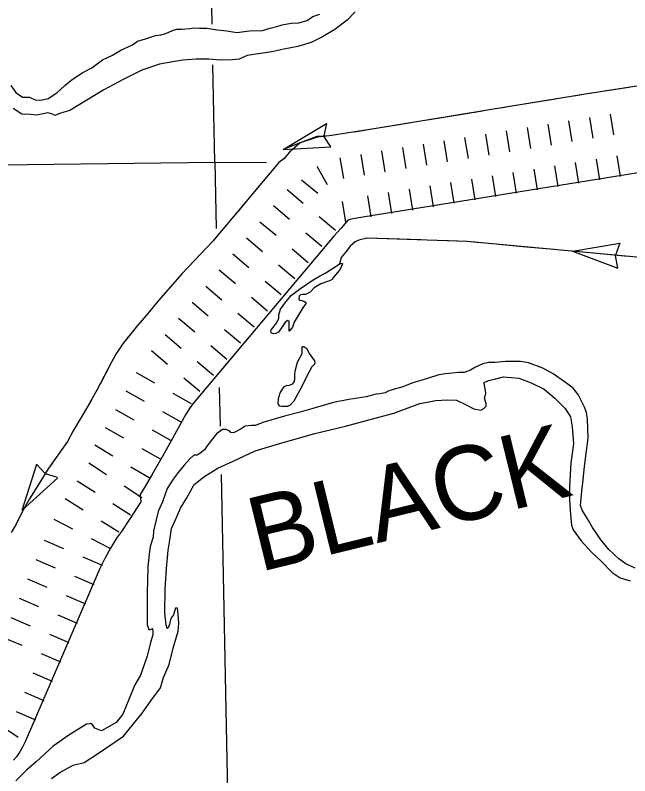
# Model space of a CAD drawing. Extents: x 1164457 to 1439835, y 1590918 to 1773502.
# Drawn here: x 1312624 to 1317004, y 1635733 to 1641151 of the extents above; entities that cross this region are included whole.
import ezdxf

# ---------------------------------------------------------------- set-up
doc = ezdxf.new("R2010")
doc.units = 0
for name, color, linetype in [('Level 29', 7, 'Continuous'), ('Level 35', 7, 'Continuous'), ('Level 43', 7, 'Continuous'), ('Level 5', 7, 'Continuous')]:
    doc.layers.add(name, color=color, linetype=linetype)

msp = doc.modelspace()

# ---------------------------------------------------------------- linework, layer by layer
at = {"layer": 'Level 29'}
for p, q in [((1316567.5, 1640398.1), (1316591.3, 1640250)), ((1316567.5, 1640398.1), (1316591.3, 1640250)), ((1316715.6, 1640421.9), (1316739.4, 1640273.9)), ((1316863.7, 1640445.8), (1316887.5, 1640297.7)), ((1316271.3, 1640350.4), (1316295.2, 1640202.3)), ((1316419.4, 1640374.2), (1316443.3, 1640226.1)), ((1315975.1, 1640302.6), (1315999, 1640154.6)), ((1316123.2, 1640326.5), (1316147.1, 1640178.4)), ((1316123.2, 1640326.5), (1316147.1, 1640178.4)), ((1315530.9, 1640231.1), (1315554.7, 1640083)), ((1315678.9, 1640254.9), (1315702.8, 1640106.8)), ((1315678.9, 1640254.9), (1315702.8, 1640106.8)), ((1315827, 1640278.8), (1315850.9, 1640130.7)), ((1315234.7, 1640183.4), (1315258.5, 1640035.3)), ((1315234.7, 1640183.4), (1315258.5, 1640035.3)), ((1315382.8, 1640207.2), (1315406.6, 1640059.1)), ((1314938.5, 1640135.6), (1314962.4, 1639987.5)), ((1315086.6, 1640159.5), (1315110.4, 1640011.4)), ((1316763.3, 1640125.8), (1316787.2, 1639977.7)), ((1316911.4, 1640149.6), (1316935.2, 1640001.5)), ((1314773.1, 1640075.7), (1314847.9, 1639945.6)), ((1316467.1, 1640078), (1316491, 1639930)), ((1316615.2, 1640101.9), (1316639.1, 1639953.8)), ((1316615.2, 1640101.9), (1316639.1, 1639953.8)), ((1316170.9, 1640030.3), (1316194.8, 1639882.2)), ((1316170.9, 1640030.3), (1316194.8, 1639882.2)), ((1316319, 1640054.2), (1316342.9, 1639906.1)), ((1314663.4, 1639977.1), (1314779.5, 1639882.1)), ((1315874.8, 1639982.6), (1315898.6, 1639834.5)), ((1316022.8, 1640006.5), (1316046.7, 1639858.4)), ((1314561.2, 1639909.4), (1314675.9, 1639812.8)), ((1315430.5, 1639911), (1315454.3, 1639762.9)), ((1315578.6, 1639934.9), (1315602.4, 1639786.8)), ((1315726.7, 1639958.8), (1315750.5, 1639810.7)), ((1315726.7, 1639958.8), (1315750.5, 1639810.7)), ((1315134.3, 1639863.3), (1315158.2, 1639715.2)), ((1315282.4, 1639887.2), (1315306.3, 1639739.1)), ((1315282.4, 1639887.2), (1315306.3, 1639739.1)), ((1314954.3, 1639823.5), (1314978.2, 1639675.4)), ((1314464.6, 1639794.7), (1314579.3, 1639698.1)), ((1314790.7, 1639716.2), (1314905.4, 1639619.6)), ((1314368, 1639679.9), (1314482.7, 1639583.3)), ((1314368, 1639679.9), (1314482.7, 1639583.3)), ((1314694.1, 1639601.5), (1314808.8, 1639504.9)), ((1314271.4, 1639565.2), (1314386.1, 1639468.6)), ((1314597.5, 1639486.7), (1314712.2, 1639390.1)), ((1314597.5, 1639486.7), (1314712.2, 1639390.1)), ((1314174.8, 1639450.4), (1314289.5, 1639353.8)), ((1314500.9, 1639372), (1314615.6, 1639275.3)), ((1314078.2, 1639335.7), (1314192.9, 1639239)), ((1314078.2, 1639335.7), (1314192.9, 1639239)), ((1314404.3, 1639257.2), (1314519, 1639160.6)), ((1313981.6, 1639220.9), (1314096.3, 1639124.3)), ((1313885, 1639106.1), (1313999.7, 1639009.5)), ((1314307.7, 1639142.4), (1314422.4, 1639045.8)), ((1314307.7, 1639142.4), (1314422.4, 1639045.8)), ((1313788.4, 1638991.4), (1313903.1, 1638894.8)), ((1313788.4, 1638991.4), (1313903.1, 1638894.8)), ((1314211.1, 1639027.7), (1314325.8, 1638931.1)), ((1313691.8, 1638876.6), (1313806.5, 1638780)), ((1314114.5, 1638912.9), (1314229.2, 1638816.3)), ((1314017.9, 1638798.2), (1314132.6, 1638701.6)), ((1314017.9, 1638798.2), (1314132.6, 1638701.6)), ((1313595, 1638761.6), (1313709.9, 1638665.2)), ((1313921.3, 1638683.4), (1314036, 1638586.8)), ((1313485, 1638605.2), (1313615.6, 1638531.5)), ((1313485, 1638605.2), (1313615.6, 1638531.5)), ((1313824.8, 1638568.7), (1313939.6, 1638472.3)), ((1313411.3, 1638474.6), (1313541.9, 1638400.9)), ((1313746.2, 1638457.8), (1313876.9, 1638384.1)), ((1313746.2, 1638457.8), (1313876.9, 1638384.1)), ((1313337.5, 1638342), (1313468.7, 1638269.3)), ((1313672.5, 1638327.2), (1313803.2, 1638253.5)), ((1313264.8, 1638213.5), (1313395.3, 1638139.4)), ((1313264.8, 1638213.5), (1313395.3, 1638139.4)), ((1313599.9, 1638196.6), (1313731.1, 1638123.9)), ((1313192, 1638089.1), (1313320.5, 1638011.6)), ((1313525.7, 1638065.3), (1313656.2, 1637991.3)), ((1313525.7, 1638065.3), (1313656.2, 1637991.3)), ((1313149.6, 1637961.9), (1313275.1, 1637879.7)), ((1313449, 1637934.2), (1313577.4, 1637856.7)), ((1313066.6, 1637834.2), (1313192.9, 1637753.2)), ((1313066.6, 1637834.2), (1313192.9, 1637753.2)), ((1313400.5, 1637797.4), (1313525.9, 1637715.1)), ((1312980.9, 1637707.3), (1313108.3, 1637628.2)), ((1313319.2, 1637672.3), (1313445.5, 1637591.4)), ((1313319.2, 1637672.3), (1313445.5, 1637591.4)), ((1312898.4, 1637560.3), (1313032, 1637492)), ((1313235.8, 1637549), (1313363.2, 1637469.9)), ((1313165.5, 1637423.7), (1313299, 1637355.3)), ((1312829.4, 1637410.4), (1312967.2, 1637351.2)), ((1312829.4, 1637410.4), (1312967.2, 1637351.2)), ((1312770.2, 1637272.6), (1312908, 1637213.4)), ((1313105, 1637292), (1313242.8, 1637232.8)), ((1313105, 1637292), (1313242.8, 1637232.8)), ((1313045.8, 1637154.2), (1313183.6, 1637095)), ((1312710.9, 1637134.8), (1312848.8, 1637075.6)), ((1312651.7, 1636997), (1312789.6, 1636937.8)), ((1312651.7, 1636997), (1312789.6, 1636937.8)), ((1312986.6, 1637016.4), (1313124.4, 1636957.2)), ((1312927.4, 1636878.6), (1313065.2, 1636819.3)), ((1312927.4, 1636878.6), (1313065.2, 1636819.3)), ((1312592.5, 1636859.2), (1312730.3, 1636799.9)), ((1312533.3, 1636721.3), (1312671.1, 1636662.1)), ((1312868.2, 1636740.7), (1313006, 1636681.5)), ((1312808.9, 1636602.9), (1312946.8, 1636543.7)), ((1312749.7, 1636465.1), (1312887.6, 1636405.9)), ((1312749.7, 1636465.1), (1312887.6, 1636405.9)), ((1312690.5, 1636327.3), (1312828.3, 1636268.1)), ((1312631.3, 1636189.5), (1312769.1, 1636130.3)), ((1312521, 1636092), (1312644.5, 1636006.9))]:
    msp.add_line(p, q, dxfattribs=at)
msp.add_lwpolyline([(1320619.9, 1640600.7), (1315100.2, 1639711.4), (1315045.3, 1639702.4), (1315008.4, 1639696.4), (1314994.5, 1639690.4), (1314985.5, 1639679.5), (1314947.6, 1639634.6), (1314895.8, 1639577.7), (1313951.5, 1638456), (1313888.7, 1638381.2), (1313866.7, 1638348.3), (1313837.8, 1638303.4), (1313746.1, 1638140.8), (1313674.8, 1638012.1), (1313604, 1637887.4), (1313552.1, 1637798.6), (1313514.2, 1637735.8), (1313520, 1637685), (1313439.8, 1637562.7), (1313382, 1637472.5), (1313346.2, 1637424.6), (1313302.5, 1637354.2), (1313264.8, 1637285.1), (1313226.3, 1637209.9), (1312695.3, 1635974.1), (1312676.1, 1635936.3), (1312656.7, 1635902.9), (1312632.3, 1635867.6), (1312611, 1635843.3)], dxfattribs=at)
at = {"layer": 'Level 35'}
for points in [[(1315046.3, 1641175.2), (1314990.1, 1641116.3), (1314901, 1641047.7), (1314813.3, 1640995.6), (1314732.5, 1640955.9), (1314637.9, 1640928.5), (1314537.9, 1640907.9), (1314451.6, 1640888.7), (1314357.7, 1640876.4), (1314276.9, 1640864), (1314220.7, 1640838), (1314171.4, 1640832.5), (1314086.4, 1640831.1), (1314004.2, 1640838), (1313912.4, 1640838), (1313817.8, 1640829.8), (1313747.9, 1640817.4)], [(1314525.6, 1641082), (1314590, 1641094.3), (1314644.8, 1641095.7), (1314705.1, 1641113.5), (1314744.8, 1641140.9), (1314794.1, 1641158.8)], [(1312593.2, 1640650.7), (1312627.5, 1640599.9), (1312676.8, 1640565.7), (1312726.1, 1640565.7), (1312765.9, 1640547.8), (1312807, 1640545.1), (1312857.7, 1640557.4), (1312920.2, 1640598.6), (1312977.7, 1640650.7), (1313021.1, 1640684.9), (1313101, 1640739.8), (1313169.5, 1640776.8), (1313246.3, 1640833), (1313316.2, 1640865.9), (1313376.5, 1640901.5), (1313458.7, 1640938.5), (1313496.6, 1640964.6), (1313551.4, 1640982.4), (1313624.1, 1641005.6), (1313662.4, 1641011.2), (1313696.7, 1641019.4), (1313746, 1641041.3), (1313776.2, 1641050.9), (1313813.2, 1641052.3), (1313868.9, 1641054.9), (1313894.2, 1641060.4), (1313936.5, 1641057.8), (1313988.6, 1641057.8), (1314063.9, 1641046.8), (1314131.7, 1641039.9), (1314204.4, 1641028.4), (1314293.5, 1641039.3), (1314386.6, 1641042.6), (1314441.4, 1641059.1), (1314489.4, 1641070.1), (1314525.6, 1641082)], [(1313747.9, 1640817.4), (1313653.1, 1640801.2), (1313527.1, 1640758.7), (1313396.9, 1640695.6), (1313254.4, 1640618.9), (1313013.2, 1640472.2), (1312947.4, 1640453), (1312906.3, 1640435.2), (1312888.5, 1640444.8), (1312855.6, 1640455.8), (1312777.2, 1640439.5), (1312733.7, 1640443.4), (1312672, 1640446.2), (1312610.3, 1640485.9)], [(1314957.3, 1639382), (1314953.7, 1639369.5), (1314933.9, 1639333.5), (1314891.6, 1639284), (1314881.7, 1639268.7), (1314862.9, 1639257.9), (1314800.8, 1639238.2), (1314755, 1639208.5), (1314726.2, 1639178.8), (1314692.1, 1639161.7), (1314682.2, 1639161.7), (1314672.3, 1639161.7), (1314657, 1639159), (1314647.1, 1639148.2), (1314645.3, 1639128.4), (1314648.9, 1639121.2), (1314666.9, 1639117.6), (1314684.9, 1639110.5), (1314695.7, 1639104.2), (1314695.7, 1639096.1), (1314669.6, 1639060.1), (1314612.9, 1638964.8), (1314599.5, 1638928.8), (1314578.8, 1638901.8), (1314575.2, 1638900.9), (1314575.2, 1638915.3), (1314576.1, 1638945), (1314576.1, 1638972), (1314565.3, 1638975.6), (1314544.6, 1638958.5), (1314530.2, 1638937.8), (1314499.7, 1638893.7), (1314481.7, 1638882.9), (1314464.6, 1638881.1), (1314451.1, 1638885.6), (1314444.8, 1638896.4), (1314448.4, 1638909.9), (1314461.9, 1638927), (1314482.6, 1638954)], [(1314482.6, 1638954), (1314502.4, 1638990.8), (1314503.3, 1639016), (1314514.1, 1639057.4), (1314552.7, 1639109.6), (1314592.3, 1639155.4), (1314649.8, 1639198.6), (1314740.6, 1639260.6), (1314792.7, 1639292.1), (1314833.2, 1639313.7), (1314897.9, 1639352.4), (1314933.9, 1639380.2), (1314943.8, 1639382.9), (1314957.3, 1639382)], [(1314619.6, 1638614.4), (1314636.7, 1638679.2), (1314669, 1638741.2), (1314669.9, 1638767.3), (1314669.9, 1638782.6), (1314673.5, 1638790.7), (1314681.6, 1638791.6), (1314703.2, 1638776.3), (1314718.5, 1638741.2), (1314757.1, 1638688.2), (1314758.9, 1638676.5), (1314757.1, 1638663.9), (1314738.3, 1638646.8), (1314699.6, 1638574), (1314667.2, 1638505.6)], [(1317043.2, 1637211.8), (1316975.6, 1637242.9), (1316926.3, 1637277.6), (1316853.7, 1637345.3), (1316800.7, 1637411.1), (1316738.6, 1637500.6), (1316702.1, 1637562.8), (1316665.5, 1637624.9), (1316652.7, 1637657.8), (1316661.9, 1637760.2), (1316669.2, 1637820.5), (1316682, 1637935.7), (1316694.8, 1638047.2), (1316707.6, 1638136.7), (1316705.7, 1638208), (1316702.1, 1638272), (1316694.8, 1638319.5), (1316680.1, 1638359.7), (1316660, 1638401.8), (1316636.3, 1638449.3), (1316599.7, 1638495), (1316544.9, 1638533.4), (1316457.2, 1638595.5), (1316384.1, 1638635.7), (1316282.7, 1638674), (1316226.1, 1638685), (1316182.2, 1638683.2), (1316118.3, 1638685), (1316041.5, 1638677.7), (1315995.8, 1638677.7), (1315955.6, 1638666.7), (1315904.5, 1638642.9), (1315867.9, 1638622.8), (1315822.3, 1638604.6), (1315785.7, 1638604.6), (1315734.6, 1638600.9), (1315689.8, 1638595.7), (1315643.2, 1638588.1), (1315562.8, 1638562.5), (1315451.3, 1638529.6), (1315385.6, 1638504), (1315317.9, 1638483.9), (1315281.4, 1638472.9), (1315261.3, 1638460.1), (1315222.9, 1638452.8), (1315195.5, 1638451), (1315125.2, 1638432.7), (1315000.9, 1638412.6), (1314893.1, 1638390.7), (1314745.1, 1638348.6), (1314644.6, 1638319.4), (1314542.3, 1638295.6), (1314388.8, 1638249.9), (1314335.8, 1638228), (1314308.4, 1638228), (1314262.7, 1638222.5), (1314235.3, 1638204.2), (1314185, 1638178.9), (1314164.1, 1638175), (1314153.1, 1638187.8)], [(1314667.2, 1638505.6), (1314610.6, 1638401.3), (1314583.6, 1638372.5), (1314564.7, 1638362.6), (1314545, 1638362.6), (1314522.5, 1638362.6), (1314510.8, 1638366.2), (1314499.1, 1638377), (1314497.3, 1638392.3), (1314499.1, 1638414.8), (1314504.5, 1638436.4), (1314512.6, 1638460.7), (1314527.9, 1638487.6), (1314543.2, 1638504.7), (1314557.6, 1638511.9), (1314578.2, 1638515.5), (1314601.6, 1638524.5), (1314612.4, 1638538), (1314616.9, 1638556), (1314616, 1638577.6), (1314616, 1638590.2), (1314619.6, 1638614.4)], [(1313529.6, 1636178.1), (1313557.7, 1636220.3), (1313590.7, 1636266.1), (1313658.3, 1636359.3), (1313680.2, 1636432.5), (1313720.4, 1636525.7), (1313749.6, 1636642.7), (1313784.3, 1636763.3), (1313789.8, 1636820), (1313784.3, 1636884), (1313780.7, 1636926), (1313766.1, 1636926), (1313760.6, 1636913.2), (1313751.5, 1636878.5), (1313738.7, 1636860.2), (1313729.5, 1636843.7), (1313725.9, 1636823.6), (1313724, 1636810.8), (1313714.9, 1636787.1), (1313705.8, 1636781.6), (1313700.3, 1636807.2), (1313691.2, 1636891.3), (1313693, 1637061.3), (1313702.1, 1637209.3), (1313713.1, 1637339.1), (1313725.9, 1637410.4), (1313738.7, 1637494.5), (1313773.4, 1637573.1), (1313800.8, 1637638.7), (1313846.5, 1637712.5), (1313899.5, 1637807.6), (1313974.4, 1637867.9), (1314068.6, 1637923.8), (1314176.4, 1637973.2), (1314334.3, 1638047), (1314517.1, 1638101.9), (1314760.1, 1638171.3), (1314978.6, 1638222.5), (1315126.6, 1638262.7), (1315322.1, 1638315.7), (1315506.7, 1638385.2), (1315621.8, 1638407.1), (1315702.2, 1638410.8), (1315769.8, 1638408.9), (1315838.5, 1638376), (1315893.3, 1638346.8), (1315941.9, 1638338), (1315964.6, 1638348.6), (1315979.2, 1638365.1), (1315981, 1638383.4), (1315968.2, 1638425.4), (1315977.4, 1638452.8), (1315974.8, 1638478.7), (1315968.2, 1638513.1), (1315966.4, 1638533.2), (1315997.5, 1638547.9), (1316038.8, 1638559.1), (1316103.4, 1638573.5), (1316213.1, 1638564.3), (1316300.8, 1638531.4), (1316394, 1638485.7), (1316468.9, 1638423.6), (1316543.7, 1638349.3), (1316581.4, 1638288.6), (1316592.4, 1638217.3), (1316602.3, 1638096.4), (1316583.3, 1637963.2), (1316573, 1637794.8), (1316573, 1637696.1), (1316580.4, 1637593.7), (1316589.5, 1637516.9), (1316600.5, 1637484), (1316657.1, 1637405.4), (1316730.2, 1637326.8), (1316799.1, 1637261.6), (1316877.6, 1637181.1), (1316936.1, 1637142.8), (1317007.4, 1637120.8)], [(1314153.1, 1638187.8), (1314127.5, 1638198.8), (1314100.1, 1638198.8), (1314058.1, 1638167.7), (1313997.8, 1638089.1), (1313973.8, 1638055.4), (1313940.9, 1638029.8), (1313921.4, 1638016), (1313897.6, 1638016), (1313868.4, 1637990.4), (1313828.2, 1637944.7), (1313784.4, 1637893.5), (1313749.6, 1637846), (1313707.6, 1637778.3), (1313672.9, 1637683.3), (1313643.7, 1637615.7), (1313627.2, 1637546.2), (1313608.9, 1637476.7), (1313607.1, 1637432.9), (1313585.2, 1637365.2), (1313579.7, 1637312.2), (1313568.7, 1637220.3), (1313566.9, 1637123.4), (1313563.3, 1637037.5), (1313563.3, 1636969.9), (1313563.3, 1636904.1), (1313563.3, 1636860.2), (1313563.3, 1636807.2), (1313576, 1636774.3), (1313587, 1636774.3), (1313601.6, 1636781.6), (1313605.3, 1636759.7), (1313605.3, 1636737.7), (1313588.8, 1636681.1), (1313565.1, 1636586), (1313517.6, 1636448.9), (1313475.5, 1636381.3), (1313470.6, 1636375.2)], [(1313475.5, 1636381.3), (1313391.7, 1636172.4), (1313343.3, 1636111.9), (1313238.9, 1636053.1), (1313192.2, 1636072.5), (1313178.1, 1636093.7), (1313164, 1636105.4), (1313152.3, 1636103), (1313132.3, 1636101.1), (1313005.6, 1636021.3), (1312894.2, 1635943.4), (1312772.2, 1635833.1), (1312704.2, 1635772.1), (1312629.1, 1635697)], [(1312883.7, 1635713.1), (1312943, 1635756), (1313037.2, 1635807.2), (1313114.5, 1635827.5), (1313218.3, 1635894), (1313395.8, 1636015), (1313529.6, 1636178.1)]]:
    msp.add_lwpolyline(points, dxfattribs=at)
at = {"layer": 'Level 43'}
for p, q in [((1314533.5, 1640193.4), (1314842, 1640380.3)), ((1314842, 1640380.3), (1314823.4, 1640290.9)), ((1314873.1, 1640213.7), (1314823.5, 1640289.7)), ((1314533.5, 1640193.4), (1314873.1, 1640213.7)), ((1316595.7, 1639468.9), (1316934, 1639526.8)), ((1316934, 1639526.8), (1316902.3, 1639441.1)), ((1316595.7, 1639468.9), (1316917.6, 1639349.9)), ((1316917.6, 1639349.9), (1316902.2, 1639439.9)), ((1312672.9, 1637625.2), (1312778, 1637951.9)), ((1312775.1, 1637951.6), (1312837.8, 1637885.1)), ((1312672.9, 1637625.2), (1312927.3, 1637855.6)), ((1312926.3, 1637858.4), (1312838.8, 1637884.5))]:
    msp.add_line(p, q, dxfattribs=at)
for points in [[(1319926, 1641108.5), (1319794, 1641092.3), (1319578.5, 1641050.3), (1318751.7, 1640924.6), (1318162.9, 1640826.4), (1317527.4, 1640719), (1316716.2, 1640593.4), (1316147.9, 1640499.3)], [(1316995.9, 1640636.7), (1316716.2, 1640593.4), (1316604.7, 1640574.9)], [(1316474.5, 1640553.4), (1316147.9, 1640499.3), (1316083.8, 1640488.8)], [(1316147.9, 1640499.3), (1315196.6, 1640342.9), (1314985, 1640309.4), (1314860.9, 1640292.4), (1314772.8, 1640287.5), (1314654.3, 1640240.9), (1314578.8, 1640175.2), (1314537.6, 1640128.6), (1314503, 1640100.7), (1314032.1, 1639541.6)], [(1315953.5, 1640467.4), (1315562.8, 1640403.1)], [(1315432.5, 1640381.7), (1315196.6, 1640342.9), (1315041.6, 1640318.4)], [(1314911, 1640299.3), (1314860.9, 1640292.4), (1314778.7, 1640281.6), (1314654.3, 1640240.9), (1314533.5, 1640193.4)], [(1314467.5, 1640058.5), (1314339.9, 1639907.1)], [(1314339.9, 1639907.1), (1314212.4, 1639755.7)], [(1314127.3, 1639654.7), (1314032.1, 1639541.6), (1313862.1, 1639360.9)], [(1314032.1, 1639541.6), (1313812.3, 1639308), (1313646.9, 1639121.3), (1313556.4, 1639011.3), (1313496.1, 1638939.3), (1313437.4, 1638870.1), (1313389.7, 1638806.6), (1313346.1, 1638744), (1313311.3, 1638678.4), (1313206.3, 1638480.2), (1313142, 1638365.5), (1313036.9, 1638190), (1312997.5, 1638114.6), (1312859.4, 1637919.2), (1312791, 1637808.1), (1312725.6, 1637706.7), (1312671.4, 1637608.9), (1312630.4, 1637524.6), (1312595.9, 1637464.6)], [(1315844.2, 1639538.5), (1315132.3, 1639562), (1315071.9, 1639548.1), (1315046.4, 1639536.8), (1315011.9, 1639506), (1314982.7, 1639467.4), (1314946.7, 1639424.5), (1314933.9, 1639380.2)], [(1315514.4, 1639549.4), (1315132.3, 1639562), (1315118.9, 1639558.9)], [(1315844.2, 1639538.5), (1315646.3, 1639545)], [(1318209.5, 1639319.6), (1315844.2, 1639538.5)], [(1315938.5, 1639529.7), (1315844.2, 1639538.5)], [(1315006.1, 1639498.4), (1314982.7, 1639467.4), (1314946.7, 1639424.5), (1314933.9, 1639380.2)], [(1316267.1, 1639499.3), (1316070, 1639517.6)], [(1316464.3, 1639481.1), (1316267.1, 1639499.3)], [(1316990, 1639432.4), (1316595.7, 1639468.9)], [(1313772.9, 1639263.6), (1313646.9, 1639121.3), (1313556.4, 1639011.3), (1313515.6, 1638962.6)], [(1313430.9, 1638861.4), (1313389.7, 1638806.6), (1313346.1, 1638744), (1313311.3, 1638678.4), (1313228.5, 1638522.1)], [(1313164.9, 1638406.4), (1313142, 1638365.5), (1313036.9, 1638190), (1312997.5, 1638114.6), (1312963.2, 1638066)], [(1312887, 1637958.2), (1312859.4, 1637919.2), (1312791, 1637808.1), (1312725.6, 1637706.7), (1312678.5, 1637621.8)]]:
    msp.add_lwpolyline(points, dxfattribs=at)
at = {"layer": 'Level 5'}
for points in [[(1314027.4, 1641087.6), (1313995.9, 1642722.3)], [(1314046.3, 1640103.8), (1314032.9, 1640798)], [(1311754.3, 1640074.7), (1314046.3, 1640103.8)], [(1314046.3, 1640103.8), (1314414.2, 1640102.5)], [(1314046.3, 1640103.8), (1314055.7, 1639631.9)], [(1314078.4, 1638499.2), (1314083.9, 1638222.6)], [(1314090.7, 1637878.1), (1314152.7, 1634771.6)]]:
    msp.add_lwpolyline(points, dxfattribs=at)

# ---------------------------------------------------------------- texts
at = {"layer": 'Level 35'}
msp.add_text('BLACK', height=528, rotation=13.7521, dxfattribs=at).set_placement((1314362.5, 1637182.9))

doc.saveas('drawing.dxf')
